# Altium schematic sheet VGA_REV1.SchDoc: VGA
size B; DrawnBy: CE; Engineer: CE; Organization: NATIONAL SEMICONDUCTOR; Address1: 801 E. CAMPBELL ROAD; Address2: SUITE 525; Address3: RICHARDSON, TX  75081; DocumentNumber: CADC SPAD0001; Revision: 2.0; SheetTotal: 1
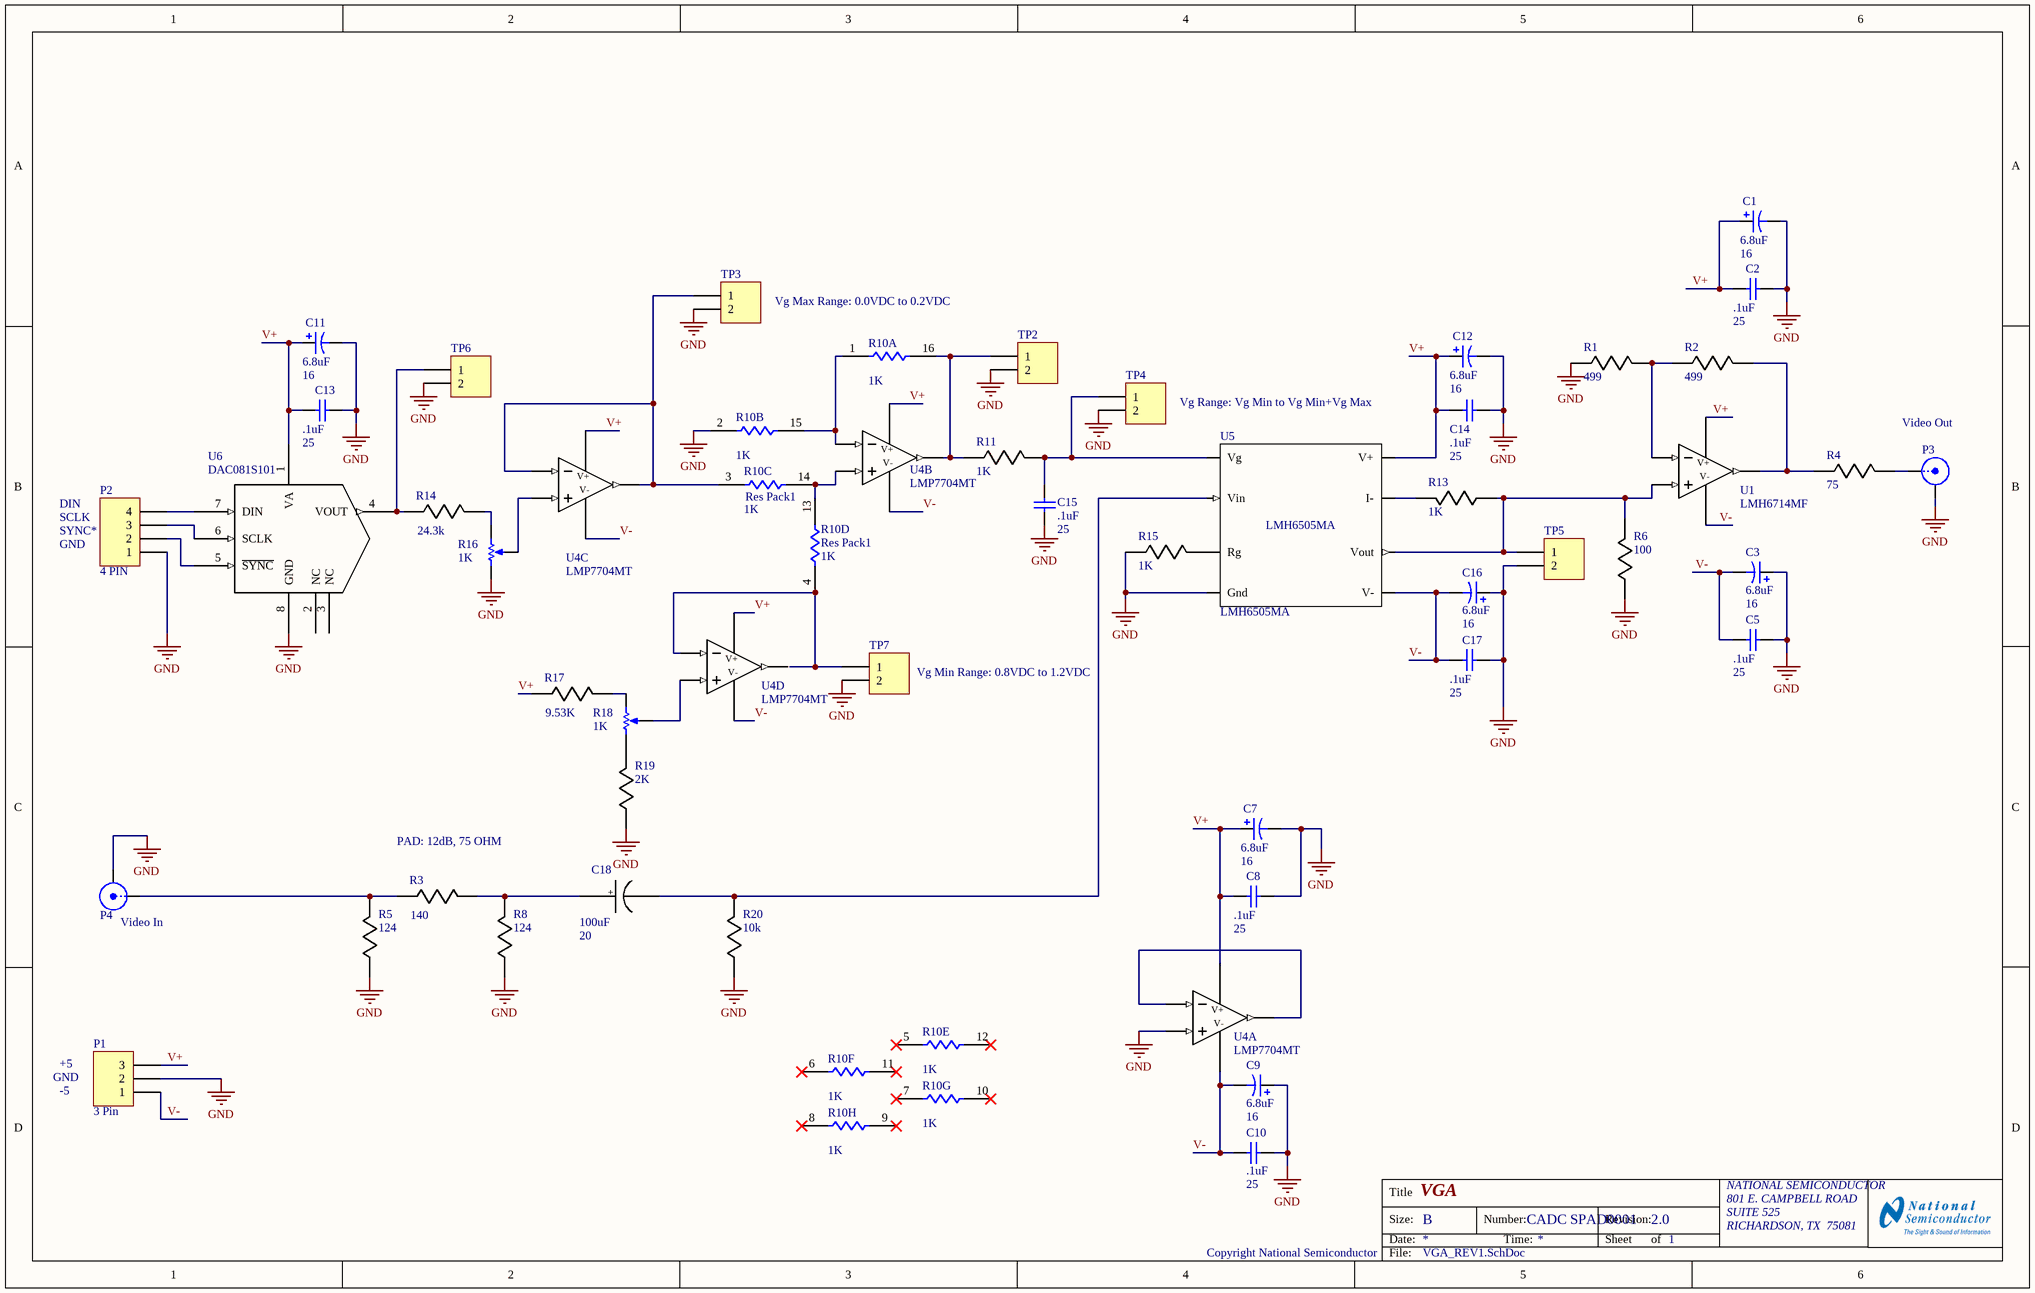
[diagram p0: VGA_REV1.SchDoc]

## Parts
C1  value 6.8uF  VDC(V): 16  [TANT-C]  (hidden comment: Cap Pol1)
C2  value .1uF  VDC(V): 25  [0805]  (hidden comment: Cap)
C3  value 6.8uF  VDC(V): 16  [TANT-C]  (hidden comment: Cap Pol1)
C5  value .1uF  VDC(V): 25  [0805]  (hidden comment: Cap)
C7  value 6.8uF  VDC(V): 16  [TANT-C]  (hidden comment: Cap Pol1)
C8  value .1uF  VDC(V): 25  [0805]  (hidden comment: Cap)
C9  value 6.8uF  VDC(V): 16  [TANT-C]  (hidden comment: Cap Pol1)
C10  value .1uF  VDC(V): 25  [0805]  (hidden comment: Cap)
C11  value 6.8uF  VDC(V): 16  [TANT-C]  (hidden comment: Cap Pol1)
C12  value 6.8uF  VDC(V): 16  [TANT-C]  (hidden comment: Cap Pol1)
C13  value .1uF  VDC(V): 25  [0805]  (hidden comment: Cap)
C14  value .1uF  VDC(V): 25  [0805]  (hidden comment: Cap)
C15  value .1uF  VDC(V): 25  [0805]  (hidden comment: Cap)
C16  value 6.8uF  VDC(V): 16  [TANT-C]  (hidden comment: Cap Pol1)
C17  value .1uF  VDC(V): 25  [0805]  (hidden comment: Cap)
C18  VDC(V): 20  [TANT-C]  (hidden comment: 100uF)
P1  3 Pin  [HDR1X3]
P2  4 PIN  [HDR1X4]
P3  75 OHM BNC  [BNC_RA CON]  (value not drawn)
P4  75 OHM BNC  [BNC_RA CON]  (value not drawn)
R1  499  [0603]
R2  499  [0603]
R3  140  [0603]
R4  75  [0603]
R5  124  [0603]
R6  100  [0603]
R8  124  [0603]
R10  1K  [SOIC16]  (parts A,B,C,D,E,F,G,H of 8)
R11  1K  [0603]
R13  1K  [0603]
R14  24.3k  [0603]
R15  1K  [0603]
R16  1K  [VR5]
R17  9.53K  [0603]
R18  1K  [VR5]
R19  2K  [0603]
R20  10k  [0603]
TP2  2 Pin  [HDR1X2]  (value not drawn)
TP3  2 Pin  [HDR1X2]  (value not drawn)
TP4  2 Pin  [HDR1X2]  (value not drawn)
TP5  2 Pin  [HDR1X2]  (value not drawn)
TP6  2 Pin  [HDR1X2]  (value not drawn)
TP7  2 Pin  [HDR1X2]  (value not drawn)
U1  LMH6714MF  [MF05A]
U4  LMP7704MT  [MTC14]  (parts A,B,C,D of 4)
U5  LMH6505MA  [SO-8]
U6  DAC081S101  [MSOP-8]

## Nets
GND: C1.2 C2.2 C3.1 C5.2 C7.2 C8.2 C9.1 C10.2 C11.2 C12.2 C13.2 C14.2 C15.1 C16.1 C17.2 P1.2 P2.1 P3.2(Y) P4.2(Y) R1.2 R5.2 R6.2 R8.2 R10.2 R15.2 R16.1(TOP) R19.2 R20.2 TP2.2 TP3.2 TP4.2 TP5.2 TP6.2 TP7.2 U4.3(+INA) U5.4(Gnd) U6.8(GND)
V+: C1.1 C2.1 C7.1 C8.1 C11.1 C12.1 C13.1 C14.1 P1.3 R17.2 U1.5(V+) U4.4(V+) U5.8(V+) U6.1(VA)
V-: C3.2 C5.1 C9.2 C10.1 C16.2 C17.1 P1.1 U1.2(V-) U4.11(V-) U5.5(V-)
NetC15_2: C15.2 R11.1 TP4.1 U5.1(Vg)
NetC18_1: C18.1(+) R3.1 R8.1
NetC18_2: C18.2(-) R20.1 U5.2(Vin)
NetP2_2: P2.2 U6.5(~{SYNC})
NetP2_3: P2.3 U6.6(SCLK)
NetP2_4: P2.4 U6.7(DIN)
NetP3_1: P3.1(X) R4.1
NetP4_1: P4.1(X) R3.2 R5.1
NetR1_1: R1.1 R2.2 U1.4(-IN)
NetR2_1: R2.1 R4.2 U1.1(OUT)
NetR6_1: R6.1 R13.2 TP5.1 U1.3(+IN) U5.6(Vout)
NetR10_1: R10.1 R10.15 U4.6(-INB)
NetR10_3: R10.3 TP3.1 U4.8(OUTC) U4.9(-INC)
NetR10_4: R10.4 TP7.1 U4.13(-IND)
NetR10_13: R10.13 R10.14 U4.5(+INB)
NetR10_16: R10.16 R11.2 TP2.1 U4.7(OUTB)
NetR13_1: R13.1 U5.7(I-)
NetR14_1: R14.1 R16.2(BOT)
NetR14_2: R14.2 TP6.1 U6.4(VOUT)
NetR15_1: R15.1 U5.3(Rg)
NetR16_3: R16.3(TAP) U4.10(+INC)
NetR17_1: R17.1 R18.2(BOT)
NetR18_1: R18.1(TOP) R19.1
NetR18_3: R18.3(TAP) U4.12(+IND)
NetU4_1: U4.1(OUTA) U4.2(-INA)

Not connected (* = marked no-connect by the designer): R10 5* 6* 7* 8* 9* 10* 11* 12*; U4 14(OUTD); U6 2(NC) 3(NC)

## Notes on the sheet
- Vg Max Range: 0.0VDC to 0.2VDC
- Vg Range: Vg Min to Vg Min+Vg Max
- Video Out
- DIN
- SCLK
- (near P2) SYNC*
- GND
- (near TP7) Vg Min Range: 0.8VDC to 1.2VDC
- PAD: 12dB, 75 OHM
- (near P4) Video In
- +5
- -5

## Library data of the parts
C1 C3 C7 C9 C11 C12 C16 = Cap Pol1: Tantalum SMT; VendorPartNumber: 595D156X0016B2T; TOL: +/-20%; Vendor: Vishay
C2 C5 C8 C10 C13-C15 C17 = Cap: Capacitor; PartNumber: VJ0805Y104KXXA; VendorPartNumber: C0805C104K3RACTU; Vendor: Kemet; TC: X7R; TOL.: +/-10%
C18 = WB_CAP_POLARIZED: Tantalum SMT; VendorPartNumber: 594D107X0020D2T; Vendor: Vishay; TOL: +/-20%
P1 = Header 3: Header, 3-Pin; Vendor: Molex
P2 = Header 4: Header, 4-Pin; Vendor: Molex
P3 P4 = BNC: BNC Elbow Connector; VendorPartNumber: 73100-0069; Vendor: Molex
R1 R2 = WB_RESISTOR: Resistor, SMD, 0603; VendorPartNumber: ERJ-3EKF4990V; TOL: 1%; Vendor: Panasonic
R3 = WB_RESISTOR: Resistor, SMD, 0603, 140 OHM; VendorPartNumber: ERJ-3EKF1400V; TOL: 1%; Vendor: Panasonic
R4 = WB_RESISTOR: Resistor, SMD, 0603; VendorPartNumber: ERJ-3EKF75R0V; TOL: 1%; Vendor: Panasonic
R5 R8 = WB_RESISTOR: Resistor, SMD, 0603; VendorPartNumber: ERJ-3EKF1240V; TOL: 1%; Vendor: Panasonic
R6 = WB_RESISTOR: Resistor, SMD, 0603; VendorPartNumber: ERJ-3EKF1000V; TOL: 1%; Vendor: Panasonic
R10 = Res Pack1: Resistor Network; VendorPartNumber: 766163102GP; Sim Note: Enter the Resistance value into parameter field.; Vendor: CTS; TOL: +/- 2%
R11 R13 R15 = WB_RESISTOR: Resistor, SMD, 0603; VendorPartNumber: ERJ-3EKF11001V; TOL: 1%; Vendor: Panasonic
R14 = WB_RESISTOR: Resistor, SMD, 0603; VendorPartNumber: ERJ-3EKF2432V; TOL: 1%; Vendor: Panasonic
R16 R18 = RPot: Potentiometer; pin to pad: 2>3 3>2; VendorPartNumber: PV374102C01B00; Sim Note: Enter the Resistance value and the set point into parameter fields.; Set Position: 0.5; Vendor: Murata; TOL: +/- 10%
R17 = WB_RESISTOR: Resistor, SMD, 0603; VendorPartNumber: ERJ-3EKF9531V; TOL: 1%; Vendor: Panasonic
R19 = WB_RESISTOR: Resistor, SMD, 0603; VendorPartNumber: ERJ-3EKF12001V; TOL: 1%; Vendor: Panasonic
R20 = WB_RESISTOR: Resistor, SMD, 0603; VendorPartNumber: ERJ-3EKF1002V; TOL: 1%; Vendor: Panasonic
TP2-TP7 = Header 2: Header, 2-Pin; Vendor: Molex
U1 = LMH6714MF: Single Wideband Video Op Amp; CompType: OpAmp IC; Vendor: National Semiconductor
U4 = LMP7704MT: Precision, CMOS Input, RRIO, Wide Supply Range Amplifiers; CompType: OpAmp IC; Vendor: National Semiconductor
U5 = LMH6505MA: Wideband, Low Power, Linear-in-dB, Variable Gain  Amplifier; Comp Type: OpAmp IC; Vendor: National Semiconductor
U6 = DAC081S101: DAC; VendorPartNumber: DAC081S101CIMM; Note: PCB Footprint - Not required; Vendor: National Semiconductor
